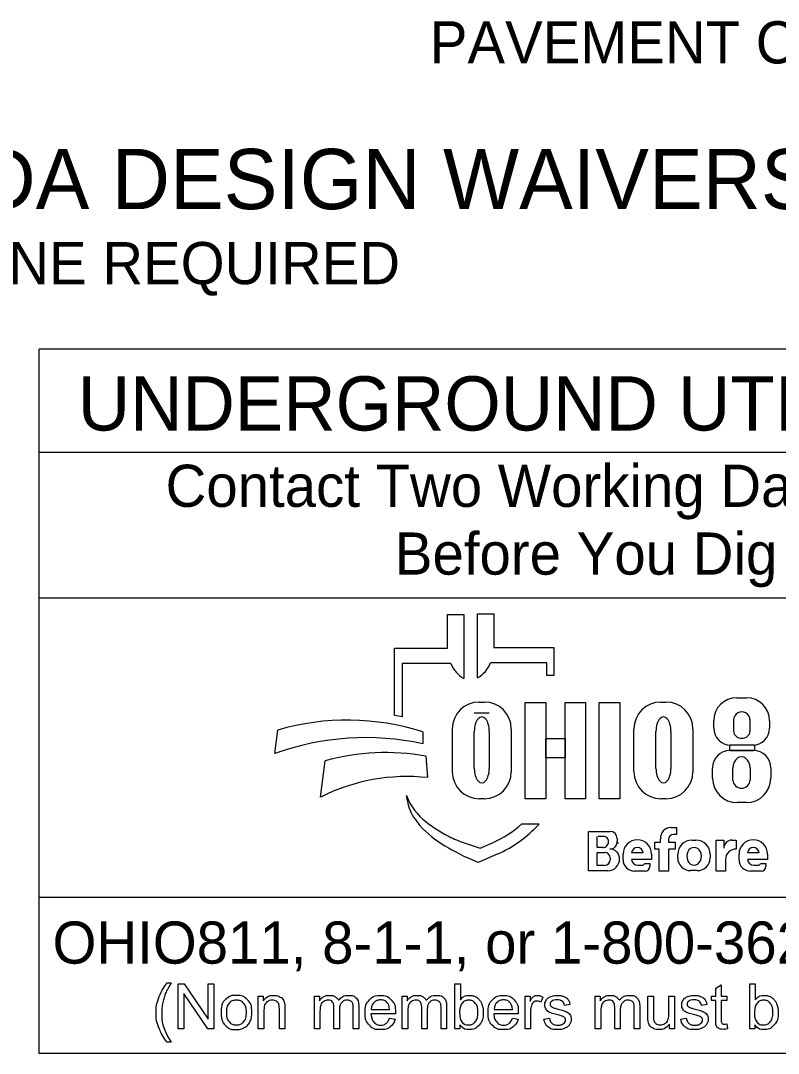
# Model space of a CAD drawing. Extents: x -3.6 to 34, y 0 to 32.8.
# Drawn here: x 2.316 to 4.831, y 1.879 to 5.307 of the extents above; entities that cross this region are included whole.
import ezdxf

# ---------------------------------------------------------------- set-up
doc = ezdxf.new("R2010")
doc.units = 0
doc.layers.add('SH_Data', color=7, linetype='Continuous')
doc.layers.add('SH_Text', color=7, linetype='Continuous')

msp = doc.modelspace()

# ---------------------------------------------------------------- linework, layer by layer
at = {"layer": 'SH_Data'}
for p, q in [((2.3775, 1.8785), (2.3775, 4.216)), ((6.6275, 4.216), (2.3775, 4.216)), ((2.3775, 3.8744), (6.6275, 3.8744)), ((2.3775, 3.391), (6.6275, 3.391)), ((6.6275, 2.3964), (2.3775, 2.3964)), ((6.6275, 1.8785), (2.3775, 1.8785))]:
    msp.add_line(p, q, dxfattribs=at)
at = {"layer": 'SH_Text'}
for p, q in [((3.7335, 3.224), (3.7335, 3.3355)), ((3.7335, 3.3355), (3.7872, 3.3355)), ((3.7872, 3.3355), (3.7872, 3.1234)), ((3.8329, 3.1258), (3.8329, 3.3378)), ((3.8329, 3.3378), (3.8865, 3.3378)), ((3.8865, 3.3378), (3.8865, 3.2263)), ((3.5576, 3.0001), (3.5576, 3.224)), ((3.5576, 3.224), (3.7335, 3.224)), ((3.8865, 3.2263), (4.0857, 3.2263)), ((4.0857, 3.2263), (4.0857, 3.1325)), ((3.5828, 3.1726), (3.5828, 2.9957)), ((3.7439, 3.1726), (3.5828, 3.1726)), ((4.0625, 3.1749), (3.8761, 3.1749)), ((4.0625, 3.1325), (4.0625, 3.1749)), ((4.0857, 3.1325), (4.0625, 3.1325)), ((4.6931, 3.0588), (4.7258, 3.0588)), ((3.8385, 3.0448), (3.8551, 3.0448)), ((4.4416, 3.0448), (4.4581, 3.0448)), ((3.8718, 3.0078), (3.822, 3.0078)), ((4.683, 2.9468), (4.683, 2.9861)), ((4.7371, 2.9861), (4.7371, 2.9468)), ((3.1602, 2.8738), (3.1696, 2.952)), ((3.7491, 2.8133), (3.7491, 2.9554)), ((3.9445, 2.9554), (3.9445, 2.8133)), ((4.3521, 2.8133), (4.3521, 2.9554)), ((4.5476, 2.9554), (4.5476, 2.8133)), ((4.6168, 2.9582), (4.6168, 2.9825)), ((4.8022, 2.9825), (4.8022, 2.9582)), ((3.6509, 2.9455), (3.6509, 2.9066)), ((3.822, 2.8247), (3.822, 2.9471)), ((3.8718, 2.9471), (3.8718, 2.8247)), ((4.425, 2.8247), (4.425, 2.9471)), ((4.4748, 2.9471), (4.4748, 2.8247)), ((4.671, 2.8839), (4.7483, 2.8839)), ((4.7462, 2.9022), (4.6728, 2.9022)), ((3.312, 2.7293), (3.3267, 2.8494)), ((3.6608, 2.8649), (3.6671, 2.7939)), ((4.6131, 2.792), (4.6131, 2.826)), ((4.6806, 2.786), (4.6806, 2.827)), ((4.7374, 2.827), (4.7374, 2.786)), ((4.8062, 2.826), (4.8062, 2.792)), ((3.5997, 2.7164), (3.5967, 2.7343)), ((3.8551, 2.7239), (3.8385, 2.7239)), ((4.4581, 2.7239), (4.4416, 2.7239)), ((4.7252, 2.711), (4.6941, 2.711)), ((3.98, 2.6405), (4.0375, 2.6405)), ((4.2013, 2.4848), (4.2013, 2.6155)), ((4.2013, 2.6155), (4.2725, 2.6155)), ((4.4739, 2.6283), (4.4934, 2.6283)), ((4.4934, 2.6283), (4.4934, 2.6053)), ((3.7816, 2.5801), (3.841, 2.5597)), ((3.841, 2.5597), (3.8821, 2.5775)), ((4.2293, 2.562), (4.2293, 2.5989)), ((4.2545, 2.5989), (4.2332, 2.5989)), ((4.2963, 2.5917), (4.2963, 2.5838)), ((4.4213, 2.5569), (4.4213, 2.5799)), ((4.4213, 2.5799), (4.4406, 2.5799)), ((4.4406, 2.5799), (4.4406, 2.5903)), ((4.4667, 2.5883), (4.4667, 2.5799)), ((4.4667, 2.5799), (4.4883, 2.5799)), ((4.4934, 2.6048), (4.4832, 2.6048)), ((4.4883, 2.5799), (4.4883, 2.5569)), ((4.5451, 2.5865), (4.5573, 2.5865)), ((4.6254, 2.4836), (4.6254, 2.5863)), ((4.6254, 2.5863), (4.6499, 2.5863)), ((4.6499, 2.5863), (4.6499, 2.5594)), ((4.6772, 2.5863), (4.691, 2.5863)), ((4.691, 2.5863), (4.691, 2.5566)), ((3.8983, 2.5401), (3.835, 2.5126)), ((4.2487, 2.562), (4.2293, 2.562)), ((4.2293, 2.5026), (4.2293, 2.5455)), ((4.2293, 2.5455), (4.2548, 2.5455)), ((4.3159, 2.5215), (4.3159, 2.54)), ((4.3824, 2.5439), (4.3439, 2.5439)), ((4.4104, 2.54), (4.4104, 2.5223)), ((4.4362, 2.5569), (4.4213, 2.5569)), ((4.4362, 2.4836), (4.4362, 2.5569)), ((4.4883, 2.5569), (4.4667, 2.5569)), ((4.4667, 2.5569), (4.4667, 2.4836)), ((4.4973, 2.5279), (4.4973, 2.5387)), ((4.6051, 2.5387), (4.6051, 2.5279)), ((4.7008, 2.5215), (4.7008, 2.54)), ((4.7674, 2.5439), (4.7288, 2.5439)), ((4.7953, 2.54), (4.7953, 2.5223)), ((3.835, 2.5126), (3.7976, 2.5291)), ((4.2729, 2.5273), (4.2729, 2.521)), ((4.3043, 2.5244), (4.3043, 2.5241)), ((4.4104, 2.5223), (4.344, 2.5223)), ((4.3649, 2.503), (4.379, 2.503)), ((4.3876, 2.5086), (4.4045, 2.5086)), ((4.4045, 2.5086), (4.4045, 2.4988)), ((4.6559, 2.5217), (4.6559, 2.4836)), ((4.7953, 2.5223), (4.7289, 2.5223)), ((4.7498, 2.503), (4.7639, 2.503)), ((4.7725, 2.5086), (4.7894, 2.5086)), ((4.7894, 2.5086), (4.7894, 2.4988)), ((4.265, 2.4848), (4.2013, 2.4848)), ((4.2546, 2.5026), (4.2293, 2.5026)), ((4.3892, 2.4836), (4.3538, 2.4836)), ((4.4667, 2.4836), (4.4362, 2.4836)), ((4.5623, 2.4851), (4.5401, 2.4851)), ((4.6559, 2.4836), (4.6254, 2.4836)), ((4.7742, 2.4836), (4.7388, 2.4836))]:
    msp.add_line(p, q, dxfattribs=at)
for points in [[(3.991, 3.0438), (4.0589, 3.0438), (4.0589, 2.7238), (3.991, 2.7238)], [(4.1231, 3.0438), (4.1911, 3.0438), (4.1911, 2.7238), (4.1231, 2.7238)], [(4.2364, 3.0438), (4.3052, 3.0438), (4.3052, 2.7238), (4.2364, 2.7238)], [(4.0589, 2.9239), (4.1231, 2.9239), (4.1231, 2.8599), (4.0589, 2.8599)], [(4.6706, 2.9023), (4.7523, 2.9023), (4.7523, 2.8838), (4.6706, 2.8838)]]:
    msp.add_lwpolyline(points, close=True, dxfattribs=at)
for points in [[(2.8021, 2.1123), (2.8153, 2.1123)], [(2.8389, 1.9596), (2.8389, 2.1098), (2.8592, 2.1098), (2.9382, 1.9919), (2.9382, 2.1098), (2.9572, 2.1098), (2.9572, 1.9596), (2.9369, 1.9596), (2.8579, 2.0776), (2.8579, 1.9596), (2.8389, 1.9596)], [(3.7743, 1.9596), (3.7573, 1.9596), (3.7573, 2.1098), (3.7757, 2.1098), (3.7757, 2.0563)], [(4.6233, 1.9915), (4.6233, 2.0542), (4.6097, 2.0542), (4.6097, 2.0685), (4.6233, 2.0685), (4.6233, 2.0954), (4.6417, 2.1065), (4.6417, 2.0685), (4.6601, 2.0685), (4.6601, 2.0542), (4.6417, 2.0542), (4.6417, 1.9904)], [(4.7534, 1.9596), (4.7363, 1.9596), (4.7363, 2.1098), (4.7548, 2.1098), (4.7548, 2.0563)], [(3.1048, 1.9596), (3.1048, 2.0685), (3.1214, 2.0685), (3.1214, 2.053)], [(3.2912, 1.9596), (3.2912, 2.0685), (3.3077, 2.0685), (3.3077, 2.0531)], [(3.5826, 1.9596), (3.5826, 2.0685), (3.5991, 2.0685), (3.5991, 2.0531)], [(3.9904, 1.9596), (3.9904, 2.0685), (4.007, 2.0685), (4.007, 2.052)], [(4.0495, 2.065), (4.043, 2.0479)], [(4.2236, 1.9596), (4.2236, 2.0685), (4.2401, 2.0685), (4.2401, 2.0531)], [(4.3979, 2.0011), (4.3979, 2.0685), (4.4164, 2.0685), (4.4164, 2.0082)], [(4.4676, 2.0102), (4.4676, 2.0685), (4.4861, 2.0685), (4.4861, 1.9596), (4.4696, 1.9596)], [(3.1932, 2.0265), (3.1932, 1.9596), (3.1748, 1.9596), (3.1748, 2.0258)], [(3.3743, 2.0228), (3.3743, 1.9596), (3.3559, 1.9596), (3.3559, 2.0303)], [(3.4388, 2.0343), (3.4388, 1.9596), (3.4203, 1.9596), (3.4203, 2.0281)], [(3.4799, 2.0244), (3.5406, 2.0244)], [(3.6657, 2.0228), (3.6657, 1.9596), (3.6473, 1.9596), (3.6473, 2.0303)], [(3.7301, 2.0343), (3.7301, 1.9596), (3.7117, 1.9596), (3.7117, 2.0281)], [(3.8879, 2.0244), (3.9486, 2.0244)], [(4.1394, 2.0403), (4.1213, 2.0379)], [(4.3067, 2.0228), (4.3067, 1.9596), (4.2883, 1.9596), (4.2883, 2.0303)], [(4.3711, 2.0343), (4.3711, 1.9596), (4.3527, 1.9596), (4.3527, 2.0281)], [(4.594, 2.0403), (4.5759, 2.0379)], [(3.1233, 2.019), (3.1233, 1.9596), (3.1048, 1.9596)], [(3.3097, 2.0161), (3.3097, 1.9596), (3.2912, 1.9596)], [(3.56, 2.0093), (3.4788, 2.0093)], [(3.5404, 1.9948), (3.5595, 1.9924)], [(3.601, 2.0161), (3.601, 1.9596), (3.5826, 1.9596)], [(3.968, 2.0093), (3.8868, 2.0093)], [(3.9484, 1.9948), (3.9675, 1.9924)], [(4.0088, 2.0166), (4.0088, 1.9596), (3.9904, 1.9596)], [(4.053, 1.9921), (4.0712, 1.995)], [(4.242, 2.0161), (4.242, 1.9596), (4.2236, 1.9596)], [(4.5076, 1.9921), (4.5258, 1.995)], [(3.7743, 1.9733), (3.7743, 1.9596)], [(4.4696, 1.9596), (4.4696, 1.9757)], [(4.6601, 1.9761), (4.6628, 1.9598)], [(4.7534, 1.9733), (4.7534, 1.9596)], [(2.8153, 1.9155), (2.8021, 1.9155)]]:
    msp.add_lwpolyline(points, dxfattribs=at)
for centre, radius, start, end in [((3.8353, 3.2093), 0.0985, 201.9296, 240.7469), ((3.7847, 3.2117), 0.0985, 299.2531, 338.0704), ((4.6931, 2.9825), 0.0763, 90, 180), ((4.7258, 2.9825), 0.0763, 0, 90), ((3.8385, 2.9554), 0.0895, 90, 180), ((3.8551, 2.9554), 0.0895, 0, 90), ((4.4416, 2.9554), 0.0895, 90, 180), ((4.4581, 2.9554), 0.0895, 0, 90), ((3.3997, 2.1659), 0.8191, 72.1402, 106.3144), ((3.4295, 2.1911), 0.8191, 79.2074, 81.0007), ((4.6728, 2.9582), 0.056, 180, 270), ((4.7462, 2.9582), 0.056, 270, 0), ((3.4628, 2.0348), 0.8919, 77.8238, 109.8274), ((4.671, 2.826), 0.0579, 90, 180), ((4.7483, 2.826), 0.0579, 0, 90), ((3.5267, 2.1451), 0.7322, 79.44, 105.8467), ((3.8385, 2.8133), 0.0895, 180, 270), ((3.8551, 2.8133), 0.0895, 270, 0), ((4.4416, 2.8133), 0.0895, 180, 270), ((4.4581, 2.8133), 0.0895, 270, 0), ((3.5987, 2.1619), 0.6357, 83.8248, 116.8021), ((4.6941, 2.792), 0.081, 180, 270), ((4.7252, 2.792), 0.081, 270, 0), ((3.7841, 2.8064), 0.2008, 201.0457, 232.5314), ((3.741, 2.7405), 0.1433, 189.6817, 216.0884), ((3.8747, 2.8379), 0.3088, 216.0884, 235.7167), ((3.9766, 3.0576), 0.5173, 232.5314, 241.794), ((3.7387, 2.9079), 0.3602, 293.4582, 312.0712), ((3.7387, 2.9079), 0.401, 293.4582, 317.8286), ((4.2725, 2.5917), 0.0238, 0, 90), ((4.4739, 2.5947), 0.0335, 90, 187.5187), ((4.0412, 3.0822), 0.6044, 235.7167, 246.2325), ((3.8914, 2.8988), 0.3371, 241.794, 250.9821), ((4.2487, 2.5807), 0.0187, 270, 2.0582), ((4.2505, 2.582), 0.0169, 357.8325, 90), ((4.2721, 2.581), 0.0243, 270, 6.6529), ((4.2827, 2.5795), 0.0175, 347.4023, 0), ((4.3631, 2.54), 0.0473, 0, 180), ((4.4832, 2.5883), 0.0165, 90, 180), ((4.5451, 2.5387), 0.0478, 90, 180), ((4.5573, 2.5387), 0.0478, 0, 90), ((4.6768, 2.5594), 0.0269, 89.2449, 180), ((4.7481, 2.54), 0.0473, 0, 180), ((4.2548, 2.5273), 0.0181, 0, 90), ((4.2722, 2.5246), 0.0321, 4.0748, 90), ((4.3632, 2.5429), 0.0193, 2.9632, 177.0368), ((4.6908, 2.5217), 0.0349, 89.6033, 180), ((4.7481, 2.5429), 0.0193, 2.9632, 177.0368), ((4.2546, 2.521), 0.0184, 270, 0), ((4.265, 2.5241), 0.0393, 270, 0), ((4.2714, 2.5244), 0.033, 0, 11.7502), ((4.3538, 2.5215), 0.038, 180, 270), ((4.3649, 2.5241), 0.021, 184.827, 270), ((4.379, 2.5124), 0.00938, 270, 335.9979), ((4.5401, 2.5279), 0.0428, 180, 270), ((4.5623, 2.5279), 0.0428, 270, 0), ((4.7388, 2.5215), 0.038, 180, 270), ((4.7498, 2.5241), 0.021, 184.827, 270), ((4.7639, 2.5124), 0.00938, 270, 335.9979), ((4.3892, 2.4988), 0.0152, 270, 0), ((4.7742, 2.4988), 0.0152, 270, 0)]:
    msp.add_arc(centre, radius, start, end, dxfattribs=at)
for centre, major_axis, ratio, start_param, end_param in [((3.8469, 2.9471), (0, 0.0484), 0.514403, 4.712389, 7.853982), ((4.4499, 2.9471), (0, 0.0484), 0.514403, 4.712389, 7.853982), ((4.71, 2.9861), (0.0271, 0), 0.969373, 0, 3.141593), ((4.71, 2.9468), (0.0271, 0), 0.818453, 3.141593, 6.283185), ((4.709, 2.827), (0, 0.0358), 0.794529, 4.712389, 7.853982), ((3.8469, 2.8247), (0, 0.0484), 0.514403, 1.570796, 4.712389), ((4.4499, 2.8247), (0, 0.0484), 0.514403, 1.570796, 4.712389), ((4.709, 2.786), (0.0284, 0), 0.959837, 3.141593, 6.283185), ((4.5517, 2.5333), (0, 0.029), 0.832186, 4.712389, 7.853982), ((4.5517, 2.5333), (0, 0.0302), 0.797287, 1.570796, 4.712389)]:
    msp.add_ellipse(centre, major_axis=major_axis, ratio=ratio, start_param=start_param, end_param=end_param, dxfattribs=at)
for points in [[(2.8021, 1.9155), (2.7869, 1.9347), (2.7763, 1.9605), (2.7657, 1.9863), (2.7657, 2.014), (2.7657, 2.0384), (2.7736, 2.0607), (2.7829, 2.0866), (2.8021, 2.1123)], [(2.8153, 2.1123), (2.8029, 2.091), (2.7989, 2.0819), (2.7927, 2.0678), (2.7891, 2.0524), (2.7847, 2.0332), (2.7847, 2.0139), (2.7847, 1.9646), (2.8153, 1.9155)], [(2.9814, 2.0141), (2.9814, 2.0443), (2.9981, 2.0588), (3.0122, 2.0709), (3.0323, 2.0709), (3.0547, 2.0709), (3.069, 2.0562), (3.0832, 2.0415), (3.0832, 2.0156), (3.0832, 1.9946), (3.0769, 1.9826), (3.0706, 1.9705), (3.0586, 1.9639), (3.0466, 1.9572), (3.0323, 1.9572), (3.0095, 1.9572), (2.9954, 1.9719), (2.9814, 1.9865), (2.9814, 2.0141)], [(3.1214, 2.053), (3.1334, 2.0709), (3.156, 2.0709), (3.1659, 2.0709), (3.1741, 2.0673), (3.1823, 2.0638), (3.1864, 2.0581), (3.1905, 2.0523), (3.1922, 2.0445), (3.1932, 2.0393), (3.1932, 2.0265)], [(3.3077, 2.0531), (3.3128, 2.0611), (3.3214, 2.066), (3.3299, 2.0709), (3.3407, 2.0709), (3.3528, 2.0709), (3.3606, 2.0658), (3.3683, 2.0608), (3.3715, 2.0518), (3.3844, 2.0709), (3.4051, 2.0709), (3.4213, 2.0709), (3.43, 2.0619), (3.4388, 2.053), (3.4388, 2.0343)], [(3.5595, 1.9924), (3.555, 1.9757), (3.5428, 1.9665), (3.5306, 1.9572), (3.5117, 1.9572), (3.4878, 1.9572), (3.4738, 1.9719), (3.4598, 1.9866), (3.4598, 2.0131), (3.4598, 2.0406), (3.474, 2.0557), (3.4881, 2.0709), (3.5106, 2.0709), (3.5324, 2.0709), (3.5463, 2.056), (3.5601, 2.0412), (3.5601, 2.0142), (3.5601, 2.0126), (3.56, 2.0093)], [(3.5991, 2.0531), (3.6042, 2.0611), (3.6127, 2.066), (3.6212, 2.0709), (3.6321, 2.0709), (3.6442, 2.0709), (3.6519, 2.0658), (3.6597, 2.0608), (3.6628, 2.0518), (3.6758, 2.0709), (3.6965, 2.0709), (3.7127, 2.0709), (3.7214, 2.0619), (3.7301, 2.053), (3.7301, 2.0343)], [(3.7757, 2.0563), (3.7874, 2.0709), (3.8055, 2.0709), (3.8155, 2.0709), (3.8245, 2.0668), (3.8335, 2.0628), (3.8392, 2.0555), (3.845, 2.0482), (3.8483, 2.0378), (3.8516, 2.0275), (3.8516, 2.0157), (3.8516, 1.9877), (3.8378, 1.9725), (3.8239, 1.9572), (3.8046, 1.9572), (3.7853, 1.9572), (3.7743, 1.9733)], [(3.9675, 1.9924), (3.963, 1.9757), (3.9508, 1.9665), (3.9386, 1.9572), (3.9196, 1.9572), (3.8958, 1.9572), (3.8818, 1.9719), (3.8678, 1.9866), (3.8678, 2.0131), (3.8678, 2.0406), (3.882, 2.0557), (3.8961, 2.0709), (3.9186, 2.0709), (3.9404, 2.0709), (3.9543, 2.056), (3.9681, 2.0412), (3.9681, 2.0142), (3.9681, 2.0126), (3.968, 2.0093)], [(4.007, 2.052), (4.0133, 2.0635), (4.0187, 2.0672), (4.0241, 2.0709), (4.0305, 2.0709), (4.0398, 2.0709), (4.0495, 2.065)], [(4.0712, 1.995), (4.0727, 1.984), (4.0798, 1.9782), (4.0868, 1.9723), (4.0995, 1.9723), (4.1122, 1.9723), (4.1184, 1.9775), (4.1245, 1.9827), (4.1245, 1.9897), (4.1245, 1.9959), (4.1191, 1.9995), (4.1153, 2.002), (4.1002, 2.0058), (4.0799, 2.0109), (4.072, 2.0146), (4.0642, 2.0184), (4.0601, 2.025), (4.0561, 2.0316), (4.0561, 2.0396), (4.0561, 2.0468), (4.0594, 2.053), (4.0628, 2.0592), (4.0685, 2.0633), (4.0728, 2.0665), (4.0803, 2.0687), (4.0877, 2.0709), (4.0962, 2.0709), (4.109, 2.0709), (4.1187, 2.0672), (4.1284, 2.0635), (4.133, 2.0572), (4.1377, 2.0509), (4.1394, 2.0403)], [(4.2401, 2.0531), (4.2452, 2.0611), (4.2537, 2.066), (4.2622, 2.0709), (4.2731, 2.0709), (4.2852, 2.0709), (4.2929, 2.0658), (4.3007, 2.0608), (4.3038, 2.0518), (4.3168, 2.0709), (4.3375, 2.0709), (4.3537, 2.0709), (4.3624, 2.0619), (4.3711, 2.053), (4.3711, 2.0343)], [(4.5258, 1.995), (4.5273, 1.984), (4.5343, 1.9782), (4.5414, 1.9723), (4.554, 1.9723), (4.5668, 1.9723), (4.5729, 1.9775), (4.5791, 1.9827), (4.5791, 1.9897), (4.5791, 1.9959), (4.5736, 1.9995), (4.5698, 2.002), (4.5548, 2.0058), (4.5345, 2.0109), (4.5266, 2.0146), (4.5188, 2.0184), (4.5147, 2.025), (4.5107, 2.0316), (4.5107, 2.0396), (4.5107, 2.0468), (4.514, 2.053), (4.5173, 2.0592), (4.5231, 2.0633), (4.5274, 2.0665), (4.5348, 2.0687), (4.5423, 2.0709), (4.5508, 2.0709), (4.5636, 2.0709), (4.5733, 2.0672), (4.583, 2.0635), (4.5876, 2.0572), (4.5922, 2.0509), (4.594, 2.0403)], [(4.7548, 2.0563), (4.7664, 2.0709), (4.7846, 2.0709), (4.7946, 2.0709), (4.8036, 2.0668), (4.8125, 2.0628), (4.8183, 2.0555), (4.8241, 2.0482), (4.8274, 2.0378), (4.8306, 2.0275), (4.8306, 2.0157), (4.8306, 1.9877), (4.8168, 1.9725), (4.803, 1.9572), (4.7836, 1.9572), (4.7644, 1.9572), (4.7534, 1.9733)], [(3.0003, 2.0141), (3.0003, 1.9931), (3.0094, 1.9827), (3.0185, 1.9723), (3.0323, 1.9723), (3.046, 1.9723), (3.0551, 1.9828), (3.0642, 1.9932), (3.0642, 2.0147), (3.0642, 2.0349), (3.0551, 2.0453), (3.0459, 2.0557), (3.0323, 2.0557), (3.0185, 2.0557), (3.0094, 2.0453), (3.0003, 2.035), (3.0003, 2.0141)], [(3.1748, 2.0258), (3.1748, 2.037), (3.1726, 2.0426), (3.1705, 2.0482), (3.165, 2.0515), (3.1595, 2.0549), (3.1521, 2.0549), (3.1404, 2.0549), (3.1318, 2.0474), (3.1233, 2.0399), (3.1233, 2.019)], [(3.3559, 2.0303), (3.3559, 2.0426), (3.3514, 2.0487), (3.3469, 2.0549), (3.3366, 2.0549), (3.3288, 2.0549), (3.3222, 2.0508), (3.3156, 2.0467), (3.3126, 2.0388), (3.3097, 2.0309), (3.3097, 2.0161)], [(3.4203, 2.0281), (3.4203, 2.0392), (3.4185, 2.0441), (3.4168, 2.0489), (3.412, 2.0519), (3.4073, 2.0549), (3.401, 2.0549), (3.3895, 2.0549), (3.3819, 2.0472), (3.3743, 2.0396), (3.3743, 2.0228)], [(3.5406, 2.0244), (3.5394, 2.0382), (3.5337, 2.0451), (3.5249, 2.0558), (3.5108, 2.0558), (3.4981, 2.0558), (3.4894, 2.0472), (3.4808, 2.0387), (3.4799, 2.0244)], [(3.6473, 2.0303), (3.6473, 2.0426), (3.6428, 2.0487), (3.6383, 2.0549), (3.628, 2.0549), (3.6202, 2.0549), (3.6136, 2.0508), (3.607, 2.0467), (3.604, 2.0388), (3.601, 2.0309), (3.601, 2.0161)], [(3.7117, 2.0281), (3.7117, 2.0392), (3.7099, 2.0441), (3.7081, 2.0489), (3.7034, 2.0519), (3.6987, 2.0549), (3.6923, 2.0549), (3.6809, 2.0549), (3.6733, 2.0472), (3.6657, 2.0396), (3.6657, 2.0228)], [(3.7741, 2.0149), (3.7741, 1.9953), (3.7794, 1.9866), (3.7881, 1.9723), (3.8029, 1.9723), (3.815, 1.9723), (3.8238, 1.9828), (3.8326, 1.9934), (3.8326, 2.0142), (3.8326, 2.0355), (3.8241, 2.0456), (3.8157, 2.0558), (3.8038, 2.0558), (3.7917, 2.0558), (3.7829, 2.0453), (3.7741, 2.0348), (3.7741, 2.0149)], [(3.9486, 2.0244), (3.9474, 2.0382), (3.9417, 2.0451), (3.9328, 2.0558), (3.9188, 2.0558), (3.9061, 2.0558), (3.8974, 2.0472), (3.8888, 2.0387), (3.8879, 2.0244)], [(4.043, 2.0479), (4.0363, 2.0519), (4.0295, 2.0519), (4.0235, 2.0519), (4.0187, 2.0482), (4.0139, 2.0446), (4.0119, 2.0381), (4.0088, 2.0283), (4.0088, 2.0166)], [(4.1213, 2.0379), (4.1201, 2.0463), (4.1142, 2.0511), (4.1083, 2.0558), (4.0975, 2.0558), (4.0848, 2.0558), (4.0794, 2.0516), (4.0739, 2.0474), (4.0739, 2.0417), (4.0739, 2.0381), (4.0762, 2.0353), (4.0785, 2.0323), (4.0833, 2.0303), (4.086, 2.0293), (4.0996, 2.0256), (4.1192, 2.0204), (4.1269, 2.0171), (4.1347, 2.0137), (4.1391, 2.0074), (4.1435, 2.001), (4.1435, 1.9916), (4.1435, 1.9824), (4.1381, 1.9743), (4.1327, 1.9661), (4.1226, 1.9617), (4.1124, 1.9572), (4.0996, 1.9572), (4.0784, 1.9572), (4.0672, 1.966), (4.0561, 1.9748), (4.053, 1.9921)], [(4.2883, 2.0303), (4.2883, 2.0426), (4.2838, 2.0487), (4.2793, 2.0549), (4.269, 2.0549), (4.2612, 2.0549), (4.2546, 2.0508), (4.248, 2.0467), (4.245, 2.0388), (4.242, 2.0309), (4.242, 2.0161)], [(4.3527, 2.0281), (4.3527, 2.0392), (4.3509, 2.0441), (4.3491, 2.0489), (4.3444, 2.0519), (4.3397, 2.0549), (4.3333, 2.0549), (4.3219, 2.0549), (4.3143, 2.0472), (4.3067, 2.0396), (4.3067, 2.0228)], [(4.5759, 2.0379), (4.5747, 2.0463), (4.5688, 2.0511), (4.5629, 2.0558), (4.5521, 2.0558), (4.5394, 2.0558), (4.5339, 2.0516), (4.5285, 2.0474), (4.5285, 2.0417), (4.5285, 2.0381), (4.5308, 2.0353), (4.533, 2.0323), (4.5378, 2.0303), (4.5406, 2.0293), (4.5542, 2.0256), (4.5737, 2.0204), (4.5815, 2.0171), (4.5893, 2.0137), (4.5937, 2.0074), (4.5981, 2.001), (4.5981, 1.9916), (4.5981, 1.9824), (4.5927, 1.9743), (4.5873, 1.9661), (4.5772, 1.9617), (4.567, 1.9572), (4.5542, 1.9572), (4.5329, 1.9572), (4.5218, 1.966), (4.5107, 1.9748), (4.5076, 1.9921)], [(4.7532, 2.0149), (4.7532, 1.9953), (4.7585, 1.9866), (4.7672, 1.9723), (4.782, 1.9723), (4.7941, 1.9723), (4.8029, 1.9828), (4.8116, 1.9934), (4.8116, 2.0142), (4.8116, 2.0355), (4.8032, 2.0456), (4.7948, 2.0558), (4.7828, 2.0558), (4.7708, 2.0558), (4.762, 2.0453), (4.7532, 2.0348), (4.7532, 2.0149)], [(3.4788, 2.0093), (3.4799, 1.9914), (3.489, 1.9819), (3.4981, 1.9723), (3.5117, 1.9723), (3.5219, 1.9723), (3.5291, 1.9777), (3.5362, 1.983), (3.5404, 1.9948)], [(3.8868, 2.0093), (3.8879, 1.9914), (3.897, 1.9819), (3.9061, 1.9723), (3.9197, 1.9723), (3.9299, 1.9723), (3.937, 1.9777), (3.9442, 1.983), (3.9484, 1.9948)], [(4.4696, 1.9757), (4.4569, 1.9572), (4.4351, 1.9572), (4.4255, 1.9572), (4.4171, 1.9609), (4.4088, 1.9646), (4.4047, 1.9702), (4.4007, 1.9758), (4.3991, 1.9839), (4.3979, 1.9893), (4.3979, 2.0011)], [(4.4164, 2.0082), (4.4164, 1.9937), (4.4175, 1.9887), (4.4192, 1.9814), (4.4249, 1.9773), (4.4305, 1.9731), (4.4388, 1.9731), (4.4471, 1.9731), (4.4543, 1.9774), (4.4616, 1.9816), (4.4646, 1.989), (4.4676, 1.9963), (4.4676, 2.0102)], [(4.6628, 1.9598), (4.655, 1.9582), (4.6488, 1.9582), (4.6388, 1.9582), (4.6333, 1.9613), (4.6278, 1.9645), (4.6255, 1.9697), (4.6233, 1.9749), (4.6233, 1.9915)], [(4.6417, 1.9904), (4.6417, 1.9825), (4.6427, 1.9802), (4.6436, 1.978), (4.6458, 1.9767), (4.648, 1.9753), (4.6521, 1.9753), (4.6551, 1.9753), (4.6601, 1.9761)]]:
    msp.add_open_spline(points, degree=3, dxfattribs=at)

# ---------------------------------------------------------------- texts
for s, height, p in [('PAVEMENT CROSS SLOPE', 0.14, (3.6744, 5.1652)), ('ADA DESIGN WAIVERS', 0.2, (1.9944, 4.6814)), ('NONE REQUIRED', 0.14, (1.9944, 4.4322)), ('UNDERGROUND UTILITIES', 0.18, (2.5057, 3.9464)), ('Contact Two Working Days', 0.14, (2.7972, 3.6929)), ('Before You Dig', 0.14, (3.5583, 3.4679)), ('OHIO811, 8-1-1, or 1-800-362-2764', 0.14, (2.422, 2.1763))]:
    msp.add_text(s, height=height, dxfattribs=at).set_placement(p)

doc.saveas('drawing.dxf')
